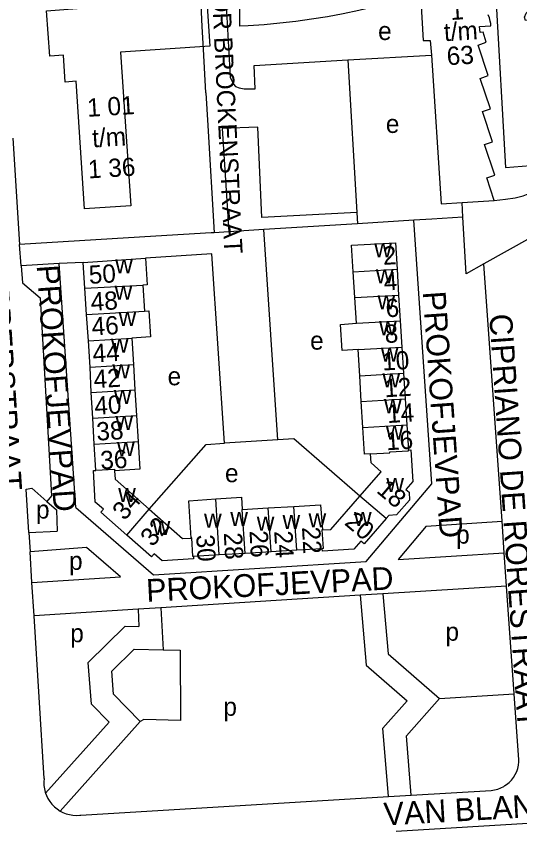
# Model space of a CAD drawing. Extents: x 159045 to 160918, y 380454 to 382516.
# Drawn here: x 159814.2 to 159924.5, y 381007.8 to 381185.5 of the extents above; entities that cross this region are included whole.
import ezdxf

# ---------------------------------------------------------------- set-up
doc = ezdxf.new("R2010")
doc.units = 0
for name, color, linetype in [('BLT_Basislijn', 7, 'Continuous'), ('BLT_Bebouwing', 7, 'Continuous'), ('BLT_Centroide', 7, 'Continuous'), ('BLT_Huisnummer', 7, 'Continuous'), ('BLT_Huisnummer_ tussenligend', 7, 'Continuous'), ('BLT_Huisnummer_reeks', 7, 'Continuous'), ('BLT_Huisnummer_zonder_bebouwing', 7, 'Continuous'), ('BLT_Onderverdeling_panden', 7, 'Continuous'), ('BLT_Plantopo', 7, 'Continuous'), ('BLT_Straatnaam', 7, 'Continuous'), ('BLT_Straatnaam_verkleind', 7, 'Continuous')]:
    doc.layers.add(name, color=color, linetype=linetype)

msp = doc.modelspace()

# ---------------------------------------------------------------- linework, layer by layer
at = {"layer": 'BLT_Basislijn'}
for p, q in [((159854.92, 381183.19), (159854.34, 381195.66)), ((159919.19, 381191.05), (159921.42, 381152.27)), ((159886.83, 381175.88), (159905.14, 381176.95)), ((159886.83, 381175.88), (159888.79, 381142.47)), ((159855.75, 381168.68), (159856.17, 381161.52)), ((159856.17, 381161.52), (159857.52, 381138.01)), ((159813.42, 381158.74), (159814.92, 381135.41)), ((159921.42, 381152.27), (159929.92, 381152.96)), ((159912.07, 381141.39), (159911.89, 381144.65)), ((159888.79, 381142.47), (159888.94, 381139.97)), ((159912.77, 381129.01), (159912.07, 381141.39)), ((159888.94, 381139.97), (159868.42, 381138.69)), ((159901.34, 381140.74), (159888.94, 381139.97)), ((159905.23, 381083), (159901.34, 381140.74)), ((159860.79, 381138.22), (159857.52, 381138.01)), ((159868.42, 381138.69), (159860.79, 381138.22)), ((159871.52, 381092.61), (159868.42, 381138.69)), ((159815.23, 381130.78), (159814.92, 381135.41)), ((159823.61, 381131.3), (159815.23, 381130.78)), ((159828.84, 381131.51), (159823.61, 381131.3)), ((159827.22, 381077.78), (159823.61, 381131.3)), ((159916.65, 381131.18), (159912.77, 381129.01)), ((159920.64, 381074.78), (159916.65, 381131.18)), ((159871.52, 381092.61), (159859.85, 381091.88)), ((159820.89, 381079.14), (159822.98, 381077.32)), ((159822.98, 381077.32), (159823.12, 381072.61)), ((159904.01, 381073.69), (159920.64, 381074.78)), ((159921.13, 381067.86), (159920.64, 381074.78)), ((159816.94, 381072.35), (159823.12, 381072.61)), ((159816.94, 381072.35), (159817.2, 381068.06)), ((159829.55, 381069.05), (159817.2, 381068.06)), ((159817.62, 381061.35), (159817.2, 381068.06)), ((159921.64, 381060.58), (159921.13, 381067.86)), ((159818.07, 381054.06), (159817.62, 381061.35)), ((159921.64, 381060.58), (159894.52, 381058.87)), ((159923.31, 381036.97), (159921.64, 381060.58)), ((159889.53, 381058.56), (159845.85, 381055.81)), ((159894.52, 381058.87), (159889.53, 381058.56)), ((159840.86, 381055.49), (159818.07, 381054.06)), ((159845.85, 381055.81), (159840.86, 381055.49)), ((159845.85, 381055.81), (159846.35, 381046.62)), ((159820.27, 381018.43), (159818.07, 381054.06)), ((159906.96, 381035.92), (159923.31, 381036.97)), ((159924.33, 381022.47), (159923.31, 381036.97)), ((159841.35, 381030.94), (159823.84, 381011.28)), ((159900.71, 381014.75), (159918.26, 381015.82)), ((159828.32, 381010.37), (159895.72, 381014.45)), ((159895.72, 381014.45), (159900.71, 381014.75)), ((159897.46, 381006.84), (159981.52, 381011.99))]:
    msp.add_line(p, q, dxfattribs=at)
for points in [[(159920.31, 381218.08), (159918.35, 381215.52), (159915.68, 381212.61), (159911.81, 381210.01), (159904.67, 381207.12), (159894.1, 381203.61), (159883.02, 381200.84), (159873.71, 381199.46), (159866.94, 381199.18), (159863.04, 381198.97), (159861.77, 381198.79), (159860.95, 381198.37), (159860.14, 381197.68), (159859.83, 381196.79), (159859.77, 381195.84), (159861.04, 381172.11), (159861.76, 381170.59), (159862.22, 381170.04), (159863.02, 381169.74), (159864.09, 381169.54), (159865.1, 381169.55), (159866.56, 381169.54), (159866.32, 381174.68), (159886.83, 381175.88)], [(159929.92, 381152.96), (159928.45, 381184.78), (159925.74, 381184.52), (159925.57, 381185.23), (159925.93, 381186.14), (159926.73, 381186.86), (159928.19, 381187.18), (159929.46, 381187.37), (159931.1, 381187.55), (159932.24, 381187.24), (159932.92, 381186.09), (159933.4, 381184.77), (159934.9, 381151.48), (159935.2, 381145.67), (159934.69, 381143.88), (159931.98, 381139.74), (159916.65, 381131.18)], [(159855.75, 381168.68), (159855.21, 381178.2), (159854.92, 381183.19)], [(159888.79, 381142.47), (159867.96, 381141.38), (159867.12, 381161.16), (159859.29, 381160.88), (159860.79, 381138.22)], [(159918.93, 381145.08), (159921.39, 381145.36), (159923.54, 381145.68), (159925.25, 381146.09), (159926.74, 381146.71), (159928.17, 381147.67), (159929.7, 381149.19), (159929.92, 381152.96)], [(159912.07, 381141.39), (159905.24, 381140.98), (159901.34, 381140.74)], [(159857.52, 381138.01), (159856.92, 381137.98), (159844.76, 381137.28), (159814.92, 381135.41)], [(159859.85, 381091.88), (159857.06, 381133.38), (159842.51, 381132.4)], [(159815.23, 381130.78), (159815.53, 381127.05), (159819.45, 381123.75), (159821.93, 381080.38), (159820.89, 381079.14)], [(159843.31, 381077.43), (159855.77, 381091.62), (159859.85, 381091.88)], [(159889.45, 381080.29), (159875.01, 381092.83), (159871.52, 381092.61)], [(159827.22, 381077.78), (159844.22, 381063.02), (159890.85, 381065.96), (159905.23, 381083)], [(159816.94, 381072.35), (159816.35, 381081.82), (159817.59, 381082.03), (159820.89, 381079.14)], [(159904.01, 381073.69), (159897.85, 381066.4), (159921.13, 381067.86)], [(159817.62, 381061.35), (159837.01, 381062.57), (159829.55, 381069.05)], [(159889.53, 381058.56), (159890.87, 381043.27), (159899.86, 381035.46)], [(159894.52, 381058.87), (159895.68, 381045.72), (159906.96, 381035.92)], [(159840.86, 381055.49), (159841.07, 381051.72)], [(159834.51, 381030.78), (159830.69, 381034.69), (159829.92, 381043.87), (159838.04, 381051.78), (159841.07, 381051.72)], [(159841.35, 381030.94), (159835.52, 381036.9), (159835.1, 381041.93), (159840.03, 381046.74), (159846.35, 381046.62)], [(159846.35, 381046.62), (159850.12, 381046.54), (159850.19, 381031.1), (159842.17, 381031.33), (159841.35, 381030.94)], [(159895.72, 381014.45), (159894.54, 381029.46), (159899.86, 381035.46)], [(159900.71, 381014.75), (159899.69, 381027.73), (159906.96, 381035.92)], [(159834.51, 381030.78), (159820.62, 381015.19)], [(159924.16, 381020.97), (159924.24, 381021.34), (159924.32, 381022.06), (159924.33, 381022.47)], [(159921.27, 381016.86), (159921.63, 381017.09), (159922.19, 381017.55), (159922.7, 381018.08), (159923.15, 381018.65), (159923.53, 381019.28), (159923.84, 381019.93), (159924.08, 381020.62), (159924.16, 381020.97)], [(159820.27, 381018.43), (159820.22, 381017.67), (159820.25, 381016.91), (159820.35, 381016.16), (159820.54, 381015.42), (159820.62, 381015.19)], [(159820.62, 381015.19), (159820.8, 381014.71), (159821.13, 381014.02), (159821.54, 381013.38), (159822.01, 381012.78), (159822.54, 381012.24), (159823.12, 381011.75), (159823.84, 381011.28)], [(159918.26, 381015.82), (159918.98, 381015.92), (159919.68, 381016.1), (159920.37, 381016.36), (159921.02, 381016.69), (159921.27, 381016.86)], [(159823.84, 381011.28), (159824.42, 381010.98), (159825.13, 381010.7), (159825.86, 381010.49), (159826.61, 381010.36), (159827.37, 381010.32), (159828.13, 381010.35), (159828.32, 381010.37)]]:
    msp.add_lwpolyline(points, dxfattribs=at)
at = {"layer": 'BLT_Bebouwing'}
for p, q in [((159904.92, 381180.17), (159905.14, 381176.95)), ((159911.89, 381144.65), (159918.93, 381145.08)), ((159897.26, 381135.82), (159897.63, 381130.02)), ((159828.84, 381131.51), (159842.51, 381132.4)), ((159829.22, 381125.86), (159828.84, 381131.51)), ((159888.36, 381123.79), (159888, 381129.44)), ((159897.63, 381130.02), (159897.98, 381124.36)), ((159829.6, 381120.09), (159829.22, 381125.86)), ((159841.89, 381126.5), (159842.25, 381120.81)), ((159888.71, 381118.16), (159888.36, 381123.79)), ((159897.98, 381124.36), (159898.34, 381118.74)), ((159829.99, 381114.33), (159829.6, 381120.09)), ((159898.34, 381118.74), (159898.7, 381112.97)), ((159839.49, 381114.9), (159839.84, 381109.13)), ((159830.38, 381108.56), (159829.99, 381114.33)), ((159898.7, 381112.97), (159899.07, 381107.2)), ((159889.44, 381106.62), (159889.07, 381112.39)), ((159830.59, 381103.03), (159830.38, 381108.56)), ((159839.84, 381109.13), (159840.18, 381103.61)), ((159889.79, 381101.03), (159889.44, 381106.62)), ((159899.07, 381107.2), (159899.42, 381101.61)), ((159830.94, 381097.38), (159830.59, 381103.03)), ((159840.18, 381103.61), (159840.53, 381097.93)), ((159890.15, 381095.34), (159889.79, 381101.03)), ((159899.42, 381101.61), (159899.78, 381095.92)), ((159831.29, 381091.7), (159830.94, 381097.38)), ((159840.53, 381097.93), (159840.88, 381092.29)), ((159831.65, 381085.99), (159831.29, 381091.7)), ((159863.71, 381077.36), (159869.39, 381077.71)), ((159869.39, 381077.71), (159875.03, 381078.05)), ((159881.25, 381068.76), (159875.67, 381068.43)), ((159858.65, 381067.41), (159853.01, 381067.07)), ((159864.32, 381067.75), (159858.65, 381067.41)), ((159870.03, 381068.09), (159864.32, 381067.75)), ((159875.67, 381068.43), (159870.03, 381068.09))]:
    msp.add_line(p, q, dxfattribs=at)
for points in [[(159863.15, 381183.27), (159863.16, 381195.11), (159867.85, 381193.77), (159868.35, 381195.86), (159874.88, 381194.43), (159875.26, 381196.54), (159881.86, 381195.47), (159882.12, 381197.6), (159888.77, 381196.9), (159888.92, 381199.03), (159895.58, 381198.7), (159895.61, 381200.84)], [(159902.74, 381190.32), (159899.4, 381189.3), (159896.03, 381188.35), (159892.64, 381187.48), (159889.23, 381186.69), (159885.8, 381185.98), (159882.36, 381185.34), (159878.91, 381184.79), (159875.44, 381184.31), (159871.96, 381183.92), (159868.48, 381183.6), (159864.99, 381183.36), (159863.15, 381183.27)], [(159902.74, 381190.32), (159903.38, 381180.1), (159904.92, 381180.17)], [(159918.2, 381183.33), (159918.15, 381183.85), (159918.05, 381184.39), (159917.86, 381185.08), (159917.61, 381185.73)], [(159918.93, 381145.08), (159917.27, 381150.04), (159919.04, 381150.64), (159916.8, 381157.31), (159918.58, 381157.93), (159916.36, 381164.61), (159918.07, 381165.16), (159915.84, 381171.82), (159917.62, 381172.44), (159915.38, 381179.11), (159917.16, 381179.76), (159916.47, 381181.95), (159915.81, 381181.91), (159915.73, 381183.17), (159918.2, 381183.33)], [(159905.14, 381176.95), (159907.29, 381144.36), (159911.89, 381144.65)], [(159888, 381129.44), (159887.64, 381135.27), (159897.26, 381135.82)], [(159842.51, 381132.4), (159842.89, 381126.57), (159841.89, 381126.5)], [(159842.25, 381120.81), (159843.25, 381120.87), (159843.61, 381115.22), (159839.49, 381114.9)], [(159889.07, 381112.39), (159885.62, 381112.18), (159885.26, 381117.87), (159888.71, 381118.16)], [(159891.82, 381089.54), (159890.51, 381089.46), (159890.15, 381095.34)], [(159899.78, 381095.92), (159900.12, 381090.39)], [(159840.88, 381092.29), (159841.25, 381086.18), (159835.73, 381085.84)], [(159900.12, 381090.39), (159900.68, 381090.42), (159901.12, 381083.52), (159899.56, 381081.75), (159900.26, 381081.13), (159900.37, 381079.44), (159897.53, 381076.2), (159895.85, 381076.08), (159895.26, 381075.39)], [(159889.45, 381080.29), (159894.16, 381085.65), (159891.95, 381087.56), (159891.82, 381089.54)], [(159838.38, 381071.76), (159832.69, 381076.78), (159833.28, 381077.45), (159831.51, 381079), (159831.09, 381085.89), (159831.64, 381085.93), (159831.65, 381085.99)], [(159835.73, 381085.84), (159835.84, 381083.98), (159843.31, 381077.43)], [(159852.48, 381071.11), (159852, 381079.25), (159857.88, 381079.7)], [(159857.88, 381079.7), (159863.55, 381080.05), (159863.71, 381077.36)], [(159881.27, 381072.88), (159883.09, 381072.99), (159889.45, 381080.29)], [(159843.31, 381077.43), (159850.64, 381071), (159852.48, 381071.11)], [(159875.03, 381078.05), (159880.88, 381078.41), (159881.27, 381072.88)], [(159895.26, 381075.39), (159890.39, 381069.82), (159889.71, 381070.42), (159888.17, 381068.64), (159881.29, 381068.21), (159881.25, 381068.76)], [(159853.01, 381067.07), (159853.05, 381066.52), (159846.19, 381066.08), (159844.39, 381067.67), (159843.8, 381066.99), (159838.38, 381071.76)]]:
    msp.add_lwpolyline(points, dxfattribs=at)
at = {"layer": 'BLT_Onderverdeling_panden'}
for p, q in [((159888, 381129.44), (159897.63, 381130.02)), ((159829.22, 381125.86), (159841.89, 381126.5)), ((159888.36, 381123.79), (159897.98, 381124.36)), ((159829.6, 381120.09), (159842.25, 381120.81)), ((159888.71, 381118.16), (159898.34, 381118.74)), ((159829.99, 381114.33), (159839.49, 381114.9)), ((159889.07, 381112.39), (159898.7, 381112.97)), ((159830.38, 381108.56), (159839.84, 381109.13)), ((159889.44, 381106.62), (159899.07, 381107.2)), ((159830.59, 381103.03), (159840.18, 381103.61)), ((159889.79, 381101.03), (159899.42, 381101.61)), ((159830.94, 381097.38), (159840.53, 381097.93)), ((159890.15, 381095.34), (159899.78, 381095.92)), ((159831.29, 381091.7), (159840.88, 381092.29)), ((159858.65, 381067.41), (159857.88, 381079.7)), ((159895.26, 381075.39), (159889.45, 381080.29)), ((159838.38, 381071.76), (159843.31, 381077.43)), ((159864.32, 381067.75), (159863.71, 381077.36)), ((159870.03, 381068.09), (159869.39, 381077.71)), ((159875.67, 381068.43), (159875.03, 381078.05))]:
    msp.add_line(p, q, dxfattribs=at)
for points in [[(159891.82, 381089.54), (159896.05, 381089.81), (159896.04, 381089.98), (159900.14, 381090.22), (159900.12, 381090.39)], [(159831.65, 381085.99), (159835.71, 381086.23), (159835.73, 381085.84)], [(159881.27, 381072.88), (159881.11, 381072.87), (159881.45, 381068.78), (159881.25, 381068.76)], [(159853.01, 381067.07), (159852.85, 381067.08), (159852.65, 381071.12), (159852.48, 381071.11)]]:
    msp.add_lwpolyline(points, dxfattribs=at)
at = {"layer": 'BLT_Plantopo'}
msp.add_lwpolyline([(159820.83, 381186.65), (159841.84, 381188.25), (159841.65, 381190.08), (159855.79, 381191.04), (159856.59, 381178.9), (159837.04, 381177.61), (159839.27, 381143.89), (159829.17, 381143.23), (159827.32, 381171.2), (159824.93, 381171.04), (159824.57, 381176.9), (159821.53, 381176.68)], close=True, dxfattribs=at)

# ---------------------------------------------------------------- texts
at = {"layer": 'BLT_Centroide'}
for s, p in [('e', (159893.47, 381180.24)), ('e', (159895.17, 381159.88)), ('w', (159892.63, 381132.62)), ('w', (159835.86, 381129.12)), ('w', (159892.99, 381126.91)), ('w', (159835.74, 381123.31)), ('w', (159893.35, 381121.25)), ('w', (159836.61, 381117.59)), ('w', (159893.7, 381115.56)), ('w', (159834.92, 381111.72)), ('e', (159878.58, 381112.39)), ('w', (159894.07, 381109.78)), ('w', (159835.25, 381106.09)), ('e', (159847.35, 381104.58)), ('w', (159894.43, 381104.12)), ('w', (159835.56, 381100.5)), ('w', (159894.78, 381098.47)), ('w', (159835.91, 381094.81)), ('w', (159895.15, 381092.69)), ('w', (159836.27, 381089.06)), ('e', (159859.92, 381083.35)), ('w', (159895.28, 381081.2)), ('w', (159836.52, 381079)), ('p', (159818.51, 381075.37)), ('w', (159855.33, 381073.36)), ('w', (159861.09, 381073.73)), ('w', (159866.88, 381072.73)), ('w', (159872.53, 381073.08)), ('w', (159878.23, 381073.42)), ('w', (159888.19, 381073.75)), ('w', (159844.07, 381071.75)), ('p', (159910.58, 381069.88)), ('p', (159825.75, 381064.13)), ('p', (159826.01, 381048.27)), ('p', (159908.24, 381048.6)), ('p', (159859.57, 381032.15))]:
    msp.add_text(s, height=4, dxfattribs=at).set_placement(p)
at = {"layer": 'BLT_Huisnummer'}
for s, rotation, p in [('2', 3.4485, (159894.62, 381130.95)), ('50', 3.4485, (159830.18, 381126.79)), ('6', 3.4485, (159895.23, 381119.46)), ('44', 3.4488, (159831.01, 381109.57)), ('10', 3.4488, (159894.48, 381107.8)), ('40', 3.4481, (159831.41, 381098.08)), ('16', 3.4481, (159895.32, 381090.33)), ('36', 3.4481, (159832.71, 381086.14)), ('18', 319.835, (159892.92, 381081.25)), ('34', 49.0384, (159837.9, 381074.76)), ('20', 319.835, (159885.91, 381074.19)), ('32', 49.0384, (159844.03, 381069)), ('26', 273.2573, (159865.29, 381072.66)), ('22', 273.2573, (159876.79, 381073.46)), ('30', 273.257, (159853.61, 381071.77))]:
    msp.add_text(s, height=4, rotation=rotation, dxfattribs=at).set_placement(p)
at = {"layer": 'BLT_Huisnummer_ tussenligend'}
for s, rotation, p in [('4', 3.4485, (159894.82, 381125.31)), ('48', 3.4485, (159830.6, 381120.88)), ('46', 3.4485, (159830.81, 381115.46)), ('8', 3.4485, (159895.02, 381113.82)), ('42', 3.4488, (159831.24, 381103.92)), ('12', 3.4488, (159894.93, 381101.94)), ('14', 3.4488, (159895.56, 381096.3)), ('38', 3.4481, (159831.85, 381092.44)), ('28', 273.2573, (159859.65, 381072.22)), ('24', 273.2573, (159870.71, 381072.6))]:
    msp.add_text(s, height=4, rotation=rotation, dxfattribs=at).set_placement(p)
at = {"layer": 'BLT_Huisnummer_reeks'}
for s, p in [('1', (159909.39, 381184.62)), ('t/m', (159908, 381179.97)), ('63', (159908.63, 381174.71))]:
    msp.add_text(s, height=4, rotation=3.4135, dxfattribs=at).set_placement(p)
at = {"layer": 'BLT_Huisnummer_zonder_bebouwing'}
for s, p in [('1 01', (159829.83, 381163.4)), ('t/m', (159830.93, 381156.71)), ('1 36', (159830, 381149.9))]:
    msp.add_text(s, height=4, rotation=3.4293, dxfattribs=at).set_placement(p)
at = {"layer": 'BLT_Straatnaam'}
for s, height, rotation, p in [('CORNELIS DOPPERSTRAAT', 5, 273.7565, (159804.55, 381171.86)), ('PROKOFJEVPAD', 5, 274.0302, (159818.64, 381130.82)), ('PROKOFJEVPAD', 5, 274.0302, (159903.25, 381125.05)), ('CIPRIANO DE RORESTRAAT', 4.9999, 273.9593, (159917.81, 381120.08)), ('PROKOFJEVPAD', 5, 2.9433, (159842.78, 381057.09)), ('VAN BLANKENBURGSTRAAT', 5, 3.2987, (159894.84, 381008.08))]:
    msp.add_text(s, height=height, rotation=rotation, dxfattribs=at).set_placement(p)
at = {"layer": 'BLT_Straatnaam_verkleind'}
msp.add_text('PASTOOR BROCKENSTRAAT', height=4, rotation=272.7535, dxfattribs=at).set_placement((159856.19, 381208.45))

doc.saveas('drawing.dxf')
